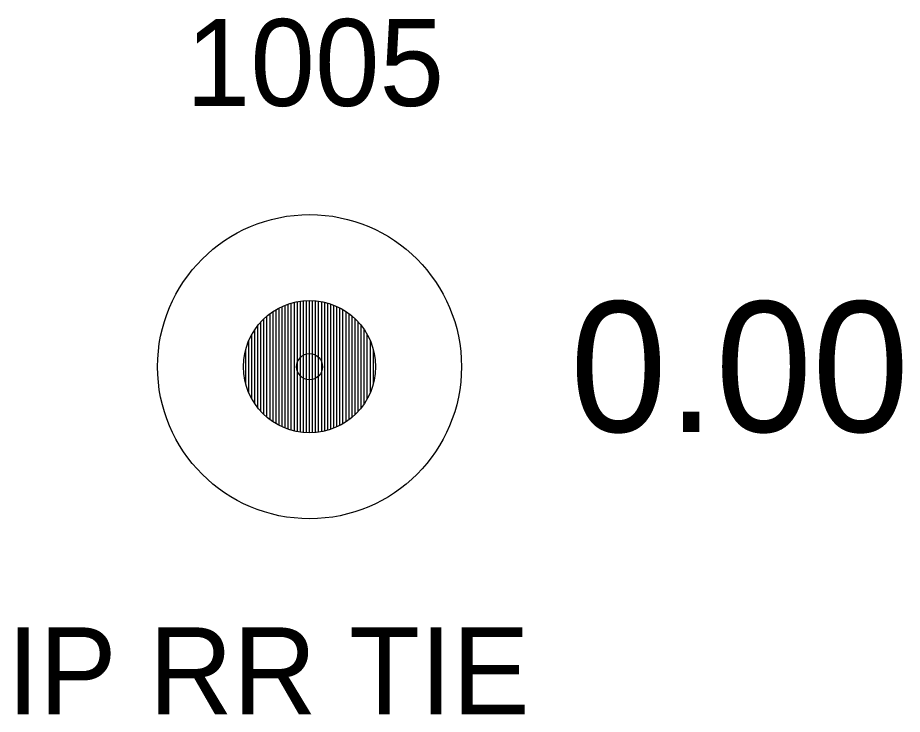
# Model space of a CAD drawing. Extents: x 2449052 to 2452984, y 1012343 to 1015262.
# Drawn here: x 2450218.54 to 2450228.72, y 1013981.04 to 1013989.06 of the extents above; entities that cross this region are included whole.
import ezdxf

# ---------------------------------------------------------------- set-up
doc = ezdxf.new("R2010")
doc.units = 0
for name, color, linetype in [('RD_EX_DV_Prop_txCode', 7, 'Continuous'), ('RD_EX_DV_PropPin', 7, 'Continuous'), ('RD_EX_TX_DV_Prop_ELEV', 7, 'Continuous'), ('RD_SMD_Locator', 7, 'Continuous')]:
    doc.layers.add(name, color=color, linetype=linetype)

msp = doc.modelspace()

# ---------------------------------------------------------------- linework, layer by layer
at = {"layer": 'RD_EX_DV_PropPin'}
for p, q in [((2450221.582, 1013984.35), (2450221.582, 1013985.735)), ((2450221.617, 1013984.335), (2450221.617, 1013985.75)), ((2450221.652, 1013984.322), (2450221.652, 1013985.763)), ((2450221.687, 1013984.311), (2450221.687, 1013985.774)), ((2450221.722, 1013984.302), (2450221.722, 1013985.783)), ((2450221.757, 1013984.294), (2450221.757, 1013985.79)), ((2450221.792, 1013984.289), (2450221.792, 1013985.796)), ((2450221.827, 1013984.285), (2450221.827, 1013985.8)), ((2450221.862, 1013984.282), (2450221.862, 1013985.803)), ((2450221.897, 1013984.281), (2450221.897, 1013985.803)), ((2450221.932, 1013984.282), (2450221.932, 1013985.803)), ((2450221.967, 1013984.285), (2450221.967, 1013985.8)), ((2450222.002, 1013984.289), (2450222.002, 1013985.796)), ((2450222.037, 1013984.294), (2450222.037, 1013985.79)), ((2450222.072, 1013984.302), (2450222.072, 1013985.783)), ((2450222.107, 1013984.311), (2450222.107, 1013985.774)), ((2450222.142, 1013984.322), (2450222.142, 1013985.763)), ((2450222.177, 1013984.335), (2450222.177, 1013985.75)), ((2450222.212, 1013984.35), (2450222.212, 1013985.735)), ((2450221.407, 1013984.46), (2450221.407, 1013985.624)), ((2450221.442, 1013984.432), (2450221.442, 1013985.652)), ((2450221.477, 1013984.408), (2450221.477, 1013985.677)), ((2450221.512, 1013984.386), (2450221.512, 1013985.699)), ((2450221.547, 1013984.367), (2450221.547, 1013985.718)), ((2450222.247, 1013984.367), (2450222.247, 1013985.718)), ((2450222.282, 1013984.386), (2450222.282, 1013985.699)), ((2450222.317, 1013984.408), (2450222.317, 1013985.677)), ((2450222.352, 1013984.432), (2450222.352, 1013985.652)), ((2450222.387, 1013984.46), (2450222.387, 1013985.624)), ((2450221.337, 1013984.527), (2450221.337, 1013985.557)), ((2450221.372, 1013984.492), (2450221.372, 1013985.593)), ((2450222.422, 1013984.492), (2450222.422, 1013985.593)), ((2450222.457, 1013984.527), (2450222.457, 1013985.557)), ((2450221.267, 1013984.616), (2450221.267, 1013985.469)), ((2450221.302, 1013984.568), (2450221.302, 1013985.516)), ((2450222.492, 1013984.568), (2450222.492, 1013985.516)), ((2450222.527, 1013984.616), (2450222.527, 1013985.469)), ((2450221.197, 1013984.744), (2450221.197, 1013985.34)), ((2450221.232, 1013984.673), (2450221.232, 1013985.412)), ((2450222.562, 1013984.673), (2450222.562, 1013985.412)), ((2450222.597, 1013984.744), (2450222.597, 1013985.34)), ((2450221.162, 1013984.846), (2450221.162, 1013985.238)), ((2450222.632, 1013984.846), (2450222.632, 1013985.238))]:
    msp.add_line(p, q, dxfattribs=at)
for radius in [1.75, 0.761]:
    msp.add_circle((2450221.897, 1013985.042), radius, dxfattribs=at)
at = {"layer": 'RD_SMD_Locator'}
msp.add_circle((2450221.897, 1013985.042), 0.15, dxfattribs=at)

# ---------------------------------------------------------------- texts
at = {"layer": 'RD_EX_DV_Prop_txCode'}
for s, p in [('1005', (2450220.472, 1013988.042)), ('IP RR TIE', (2450218.413, 1013981.042))]:
    msp.add_text(s, height=1, dxfattribs=at).set_placement(p)
at = {"layer": 'RD_EX_TX_DV_Prop_ELEV'}
msp.add_text('0.00', height=1.5, dxfattribs=at).set_placement((2450224.897, 1013984.292))

doc.saveas('drawing.dxf')
